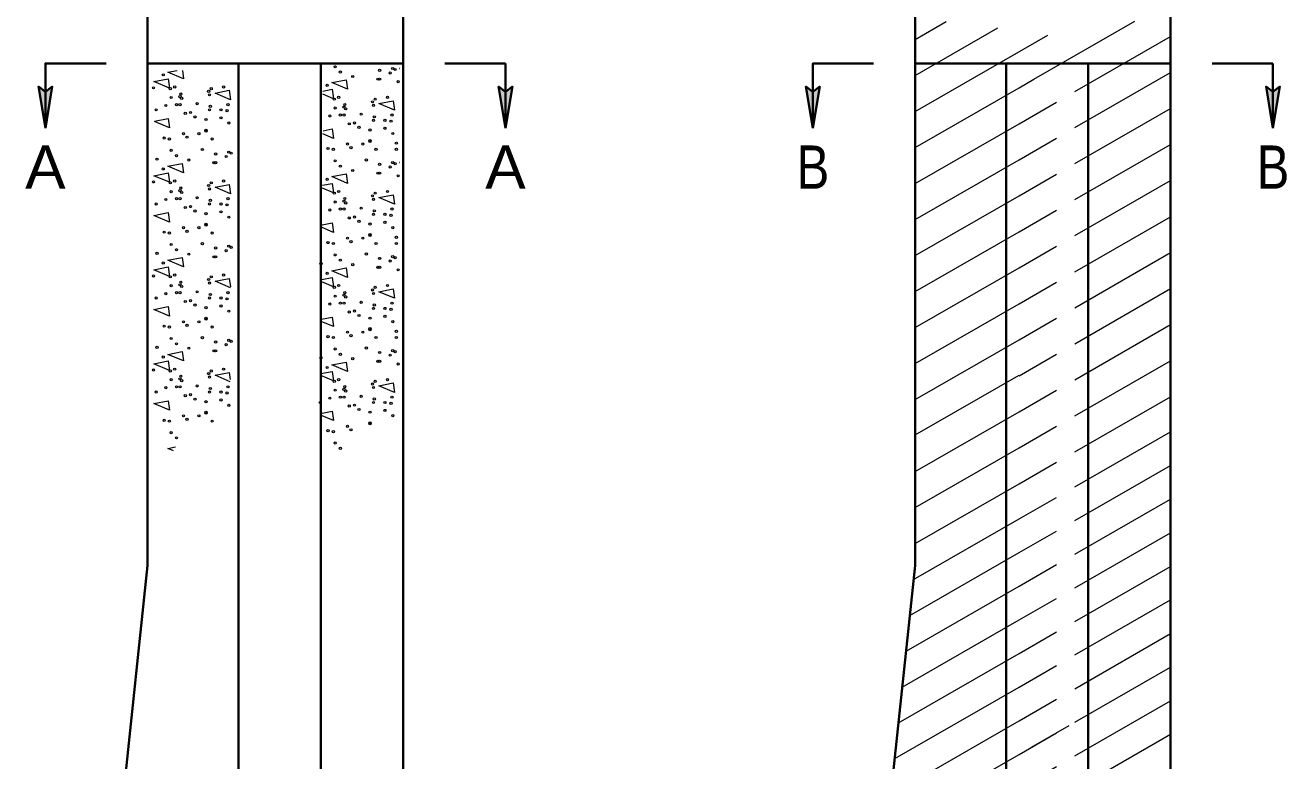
# Model space of a CAD drawing. Extents: x -43.06 to -36.2, y -1.41 to 7.25.
# Drawn here: x -39.109 to -36.195, y 3.886 to 5.585 of the extents above; entities that cross this region are included whole.
import ezdxf
from ezdxf.enums import TextEntityAlignment as Align

# ---------------------------------------------------------------- set-up
doc = ezdxf.new("R2010")
doc.units = 0
doc.header["$LTSCALE"] = 0.024
doc.linetypes.add('SHORT_DASHED', pattern=[2.7, 1.5, -1.2])
for name, color, linetype, lineweight in [('1', 7, 'Continuous', 35), ('10', 7, 'Continuous', 13), ('12', 7, 'Continuous', 53), ('6', 7, 'Continuous', 13)]:
    doc.layers.add(name, color=color, linetype=linetype, lineweight=lineweight)

msp = doc.modelspace()

# ---------------------------------------------------------------- hatches: boundary and pattern name
at = {"layer": '10'}
for points in [[(-39.06275, 5.34733), (-39.04675, 5.4435), (-39.06275, 5.4315), (-39.07875, 5.4435)], [(-37.99992, 5.34733), (-37.98392, 5.4435), (-37.99992, 5.4315), (-38.01592, 5.4435)], [(-37.28975, 5.34733), (-37.27375, 5.4435), (-37.28975, 5.4315), (-37.30575, 5.4435)], [(-36.22692, 5.34733), (-36.21092, 5.4435), (-36.22692, 5.4315), (-36.24292, 5.4435)]]:
    msp.add_hatch(color=256, dxfattribs=at).paths.add_polyline_path(points)

# ---------------------------------------------------------------- linework, layer by layer
at = {"layer": '1'}
for p, q in [((-38.43625, 5.49683), (-38.82642, 5.49683)), ((-38.61625, 5.49683), (-38.61625, 2.96633)), ((-38.43625, 5.49683), (-38.23625, 5.49683)), ((-38.23625, 5.49683), (-38.23625, 4.33667)), ((-36.84342, 5.49683), (-36.84342, 2.96133)), ((-36.65342, 5.49683), (-36.65342, 2.9635)), ((-38.82642, 4.33667), (-38.90542, 3.58917)), ((-38.23625, 4.33667), (-38.23625, 3.32433)), ((-36.46325, 4.33667), (-36.46325, 3.32017))]:
    msp.add_line(p, q, dxfattribs=at)
for points in [[(-38.82642, 7.217), (-38.82642, 5.49683), (-38.82642, 4.33667)], [(-37.05342, 7.217), (-37.05342, 5.49683), (-37.05342, 4.33667), (-37.13258, 3.58917)], [(-38.46175, 6.31517), (-38.23625, 5.97683), (-38.23625, 5.49683)], [(-36.68875, 6.31517), (-36.46325, 5.97683), (-36.46325, 5.49683), (-36.46325, 4.33667)], [(-38.42625, 5.49683), (-38.42625, 2.96633), (-38.71642, 2.96633)], [(-37.05342, 5.49683), (-36.83342, 5.49683), (-36.66342, 5.49683), (-36.46325, 5.49683)]]:
    msp.add_lwpolyline(points, dxfattribs=at)
at = {"layer": '10', "lineweight": 35}
for p, q in [((-37.99992, 5.49683), (-38.14025, 5.49683)), ((-37.99992, 5.49683), (-37.99992, 5.34733)), ((-36.22692, 5.49683), (-36.36725, 5.49683)), ((-36.22692, 5.49683), (-36.22692, 5.34733)), ((-39.07875, 5.4435), (-39.06275, 5.34733)), ((-39.07875, 5.4435), (-39.06275, 5.4315)), ((-39.04675, 5.4435), (-39.06275, 5.34733)), ((-39.04675, 5.4435), (-39.06275, 5.4315)), ((-38.01592, 5.4435), (-37.99992, 5.34733)), ((-38.01592, 5.4435), (-37.99992, 5.4315)), ((-37.98392, 5.4435), (-37.99992, 5.34733)), ((-37.98392, 5.4435), (-37.99992, 5.4315)), ((-37.30575, 5.4435), (-37.28975, 5.34733)), ((-37.30575, 5.4435), (-37.28975, 5.4315)), ((-37.27375, 5.4435), (-37.28975, 5.34733)), ((-37.27375, 5.4435), (-37.28975, 5.4315)), ((-36.24292, 5.4435), (-36.22692, 5.34733)), ((-36.24292, 5.4435), (-36.22692, 5.4315)), ((-36.21092, 5.4435), (-36.22692, 5.34733)), ((-36.21092, 5.4435), (-36.22692, 5.4315))]:
    msp.add_line(p, q, dxfattribs=at)
for points in [[(-38.92242, 5.49683), (-39.06275, 5.49683), (-39.06275, 5.34733)], [(-37.14942, 5.49683), (-37.28975, 5.49683), (-37.28975, 5.39017), (-37.28975, 5.34733)]]:
    msp.add_lwpolyline(points, dxfattribs=at)
for points in [[(-39.06275, 5.34733), (-39.04675, 5.4435), (-39.06275, 5.4315), (-39.07875, 5.4435)], [(-37.99992, 5.34733), (-37.98392, 5.4435), (-37.99992, 5.4315), (-38.01592, 5.4435)], [(-37.28975, 5.34733), (-37.27375, 5.4435), (-37.28975, 5.4315), (-37.30575, 5.4435)], [(-36.22692, 5.34733), (-36.21092, 5.4435), (-36.22692, 5.4315), (-36.24292, 5.4435)]]:
    msp.add_lwpolyline(points, close=True, dxfattribs=at)
at = {"layer": '6'}
for p, q in [((-37.05342, 5.5525), (-36.98208, 5.5935)), ((-37.05342, 5.46933), (-36.86275, 5.579)), ((-36.77958, 5.46033), (-36.54608, 5.59467)), ((-37.05342, 5.386), (-36.74725, 5.56217)), ((-36.68442, 5.43183), (-36.46325, 5.55917)), ((-38.77975, 5.47683), (-38.75842, 5.48083)), ((-38.24525, 5.48517), (-38.24442, 5.48533)), ((-38.24442, 5.48483), (-38.24525, 5.48517)), ((-36.68442, 5.34867), (-36.46325, 5.47583)), ((-37.05342, 5.30283), (-36.81342, 5.44083)), ((-36.68442, 5.26533), (-36.46325, 5.3925)), ((-37.05342, 5.21967), (-36.81342, 5.35767)), ((-36.68442, 5.18217), (-36.46325, 5.30933)), ((-38.24525, 5.26783), (-38.24492, 5.268)), ((-38.24492, 5.26767), (-38.24525, 5.26783)), ((-37.05342, 5.13633), (-36.81342, 5.27433)), ((-36.68442, 5.099), (-36.46325, 5.22617)), ((-37.05342, 5.05317), (-36.81342, 5.19117)), ((-36.68442, 5.01567), (-36.46325, 5.14283)), ((-37.05342, 4.96983), (-36.81342, 5.10783)), ((-36.68442, 4.9325), (-36.46325, 5.05967)), ((-37.05342, 4.88667), (-36.81342, 5.02467)), ((-38.63525, 4.9785), (-38.67075, 4.99367)), ((-36.68442, 4.84933), (-36.46325, 4.9765)), ((-37.05342, 4.8035), (-36.81342, 4.9415)), ((-36.68442, 4.766), (-36.46325, 4.89333)), ((-37.05342, 4.72017), (-36.81342, 4.85817)), ((-36.68442, 4.68283), (-36.46325, 4.81)), ((-38.63558, 4.76133), (-38.67075, 4.77633)), ((-37.05342, 4.63867), (-36.81342, 4.77667)), ((-36.68442, 4.59967), (-36.46325, 4.72683)), ((-37.05342, 4.55383), (-36.81342, 4.69183)), ((-36.68442, 4.5185), (-36.46325, 4.64567)), ((-38.77975, 4.60733), (-38.76208, 4.61083)), ((-38.76692, 4.602), (-38.77975, 4.60733)), ((-37.05342, 4.4705), (-36.81342, 4.6085)), ((-36.68442, 4.44083), (-36.46325, 4.568)), ((-37.05342, 4.38733), (-36.81342, 4.52533)), ((-36.68442, 4.36317), (-36.46325, 4.49033)), ((-37.05692, 4.30433), (-36.81342, 4.44433)), ((-36.68442, 4.28533), (-36.46325, 4.4125)), ((-37.06558, 4.2215), (-36.81342, 4.3665)), ((-36.68442, 4.20767), (-36.46325, 4.33483)), ((-37.07442, 4.13867), (-36.81342, 4.28883)), ((-36.68442, 4.13), (-36.46325, 4.25717)), ((-37.08308, 4.056), (-36.81342, 4.211)), ((-36.68442, 4.05217), (-36.46325, 4.17933)), ((-37.09192, 3.97317), (-36.81342, 4.13333)), ((-36.68442, 3.9745), (-36.46325, 4.10167)), ((-37.10058, 3.8905), (-36.81342, 4.05567)), ((-36.68442, 3.89667), (-36.46325, 4.024)), ((-37.10942, 3.80767), (-36.81342, 3.97783)), ((-36.68442, 3.81983), (-36.46325, 3.947)), ((-37.11825, 3.72483), (-36.81342, 3.90017))]:
    msp.add_line(p, q, dxfattribs=at)
at = {"layer": '6', "linetype": 'SHORT_DASHED'}
for p, q in [((-36.81342, 5.44083), (-36.77958, 5.46033)), ((-36.81342, 5.35767), (-36.68442, 5.43183)), ((-36.81342, 5.27433), (-36.68442, 5.34867)), ((-36.81342, 5.19117), (-36.68442, 5.26533)), ((-36.81342, 5.10783), (-36.68442, 5.18217)), ((-36.81342, 5.02467), (-36.68442, 5.099)), ((-36.81342, 4.9415), (-36.68442, 5.01567)), ((-36.81342, 4.85817), (-36.68442, 4.9325)), ((-36.81342, 4.775), (-36.68442, 4.84933)), ((-36.81342, 4.69183), (-36.68442, 4.766)), ((-36.81342, 4.6085), (-36.68442, 4.68283)), ((-36.81342, 4.52533), (-36.68442, 4.59967)), ((-36.81342, 4.44433), (-36.68442, 4.5185)), ((-36.81342, 4.3665), (-36.68442, 4.44083)), ((-36.81342, 4.28883), (-36.68442, 4.36317)), ((-36.81342, 4.211), (-36.68442, 4.28533)), ((-36.81342, 4.13333), (-36.68442, 4.20767)), ((-36.81342, 4.05567), (-36.68442, 4.13)), ((-36.81342, 3.97783), (-36.68442, 4.05217)), ((-36.81342, 3.90017), (-36.68442, 3.9745)), ((-36.78442, 3.91733), (-36.65525, 3.99167)), ((-36.81342, 3.8225), (-36.68442, 3.89667))]:
    msp.add_line(p, q, dxfattribs=at)
at = {"layer": '6'}
for points in [[(-38.74625, 5.48067), (-38.74375, 5.46133), (-38.77975, 5.47683)], [(-38.42192, 5.433), (-38.40042, 5.43717), (-38.39742, 5.41533), (-38.42192, 5.42583)], [(-38.81092, 5.3635), (-38.77908, 5.36967), (-38.77625, 5.34783), (-38.81092, 5.36267)], [(-38.42125, 5.3415), (-38.40042, 5.34567), (-38.39742, 5.32367), (-38.42142, 5.334)], [(-38.81192, 5.2375), (-38.77908, 5.244), (-38.77625, 5.22217), (-38.81192, 5.23733)], [(-38.42242, 5.2155), (-38.40042, 5.21983), (-38.39742, 5.198), (-38.42242, 5.20867)], [(-38.42325, 5.12383), (-38.40042, 5.12833), (-38.39742, 5.10633), (-38.42325, 5.1175)], [(-38.67075, 4.99367), (-38.63775, 5.00017), (-38.63525, 4.98067)], [(-38.42442, 4.99783), (-38.40042, 5.0025), (-38.39742, 4.98067), (-38.42442, 4.99217)], [(-38.42508, 4.906), (-38.40042, 4.91083), (-38.39742, 4.889), (-38.42525, 4.90083)], [(-38.67075, 4.77633), (-38.63775, 4.78283), (-38.63558, 4.76667)], [(-38.42625, 4.78017), (-38.40042, 4.78517), (-38.39742, 4.76333), (-38.42642, 4.77567)], [(-38.42708, 4.68833), (-38.40042, 4.6935), (-38.39742, 4.67167), (-38.42708, 4.68433)]]:
    msp.add_lwpolyline(points, dxfattribs=at)
for points in [[(-38.81208, 5.45483), (-38.77908, 5.46133), (-38.77625, 5.4395)], [(-38.40092, 5.45267), (-38.36775, 5.45917), (-38.36492, 5.43717)], [(-38.67075, 5.42833), (-38.63775, 5.43483), (-38.63492, 5.413)], [(-38.29208, 5.40433), (-38.25892, 5.41067), (-38.25608, 5.38883)], [(-38.77975, 5.25933), (-38.74658, 5.26583), (-38.74375, 5.244)], [(-38.67075, 5.211), (-38.63775, 5.2175), (-38.63492, 5.19567)], [(-38.40092, 5.23533), (-38.36775, 5.24183), (-38.36492, 5.21983)], [(-38.29208, 5.18683), (-38.25892, 5.19333), (-38.25608, 5.1715)], [(-38.81225, 5.14583), (-38.77908, 5.15233), (-38.77625, 5.1305)], [(-38.77975, 5.042), (-38.74658, 5.0485), (-38.74375, 5.02667)], [(-38.81225, 5.02017), (-38.77908, 5.02667), (-38.77625, 5.00483)], [(-38.40092, 5.018), (-38.36775, 5.02433), (-38.36492, 5.0025)], [(-38.29208, 4.9695), (-38.25892, 4.976), (-38.25608, 4.95417)], [(-38.81225, 4.9285), (-38.77908, 4.935), (-38.77625, 4.91317)], [(-38.81225, 4.80283), (-38.77908, 4.80933), (-38.77625, 4.78733)], [(-38.77975, 4.82467), (-38.74658, 4.83117), (-38.74375, 4.80933)], [(-38.40092, 4.8005), (-38.36775, 4.807), (-38.36492, 4.78517)], [(-38.29208, 4.75217), (-38.25892, 4.75867), (-38.25608, 4.73683)], [(-38.81225, 4.71117), (-38.77908, 4.71767), (-38.77625, 4.69583)]]:
    msp.add_lwpolyline(points, close=True, dxfattribs=at)
for centre in [(-38.39334, 5.4892), (-38.38114, 5.47695), (-38.2906, 5.48104), (-38.26028, 5.4852), (-38.25464, 5.48276), (-38.79044, 5.47055), (-38.35261, 5.46679), (-38.29464, 5.46067), (-38.2906, 5.46067), (-38.26616, 5.47495), (-38.24783, 5.45459), (-38.81284, 5.44051), (-38.77416, 5.43847), (-38.77212, 5.41811), (-38.76396, 5.44255), (-38.75175, 5.42015), (-38.74971, 5.42627), (-38.68566, 5.43235), (-38.68362, 5.42423), (-38.67954, 5.43847), (-38.65106, 5.44255), (-38.41166, 5.44643), (-38.38518, 5.41843), (-38.27228, 5.41843), (-38.80672, 5.38962), (-38.78432, 5.39978), (-38.75992, 5.40182), (-38.75175, 5.40182), (-38.74767, 5.41607), (-38.71211, 5.40386), (-38.68362, 5.38962), (-38.68158, 5.39774), (-38.65714, 5.38962), (-38.64086, 5.40182), (-38.39538, 5.41434), (-38.39334, 5.39398), (-38.37297, 5.39602), (-38.37093, 5.40214), (-38.36889, 5.39194), (-38.30688, 5.40822), (-38.30484, 5.4001), (-38.30076, 5.41434), (-38.73955, 5.38146), (-38.72731, 5.3835), (-38.71715, 5.37334), (-38.69175, 5.36722), (-38.65714, 5.3713), (-38.6429, 5.38758), (-38.40554, 5.37566), (-38.38114, 5.3777), (-38.37297, 5.3777), (-38.33333, 5.37974), (-38.30484, 5.3655), (-38.3028, 5.37362), (-38.27836, 5.3655), (-38.26412, 5.36346), (-38.26208, 5.3777), (-38.74359, 5.33465), (-38.70803, 5.33465), (-38.69175, 5.34277), (-38.69175, 5.34073), (-38.63882, 5.35906), (-38.36077, 5.35734), (-38.34853, 5.35938), (-38.33837, 5.34921), (-38.31296, 5.34309), (-38.27836, 5.34717), (-38.26004, 5.33493), (-38.7884, 5.32445), (-38.7762, 5.32241), (-38.73547, 5.32649), (-38.6775, 5.32241), (-38.36481, 5.31053), (-38.35669, 5.30237), (-38.32925, 5.31053), (-38.31296, 5.31865), (-38.31296, 5.31661), (-38.25191, 5.31257), (-38.80468, 5.2756), (-38.77212, 5.29597), (-38.75992, 5.28372), (-38.73139, 5.27356), (-38.69991, 5.29801), (-38.66938, 5.2878), (-38.64494, 5.28172), (-38.63906, 5.29197), (-38.63342, 5.28952), (-38.40962, 5.30033), (-38.39742, 5.29829), (-38.32113, 5.27388), (-38.29872, 5.29829), (-38.25191, 5.29829), (-38.79044, 5.2532), (-38.67342, 5.26744), (-38.66938, 5.26744), (-38.39334, 5.27184), (-38.38114, 5.2596), (-38.35261, 5.24944), (-38.29464, 5.24332), (-38.2906, 5.26368), (-38.2906, 5.24332), (-38.26616, 5.2576), (-38.26028, 5.26784), (-38.25464, 5.2654), (-38.81284, 5.22315), (-38.77416, 5.22111), (-38.76396, 5.22519), (-38.68566, 5.21499), (-38.67954, 5.22111), (-38.65106, 5.22519), (-38.41166, 5.22908), (-38.24783, 5.23724), (-38.77212, 5.20075), (-38.75175, 5.20279), (-38.74971, 5.20891), (-38.74767, 5.19871), (-38.71211, 5.18651), (-38.68362, 5.20687), (-38.39538, 5.19699), (-38.38518, 5.20107), (-38.37093, 5.18479), (-38.30688, 5.19087), (-38.30076, 5.19699), (-38.27228, 5.20107), (-38.80672, 5.17227), (-38.78432, 5.18243), (-38.75992, 5.18447), (-38.75175, 5.18447), (-38.73955, 5.1641), (-38.72731, 5.16615), (-38.71715, 5.15598), (-38.68362, 5.17227), (-38.68158, 5.18039), (-38.65714, 5.17227), (-38.6429, 5.17023), (-38.64086, 5.18447), (-38.40554, 5.1583), (-38.39334, 5.17663), (-38.38114, 5.16034), (-38.37297, 5.17867), (-38.37297, 5.16034), (-38.36889, 5.17459), (-38.33333, 5.16238), (-38.30484, 5.18275), (-38.3028, 5.15626), (-38.26208, 5.16034), (-38.69175, 5.14986), (-38.65714, 5.15394), (-38.63882, 5.1417), (-38.36077, 5.13998), (-38.34853, 5.14202), (-38.33837, 5.13186), (-38.30484, 5.14814), (-38.27836, 5.14814), (-38.27836, 5.12982), (-38.26412, 5.1461), (-38.7884, 5.1071), (-38.7762, 5.10506), (-38.74359, 5.1173), (-38.73547, 5.10914), (-38.70803, 5.1173), (-38.69175, 5.12542), (-38.69175, 5.12338), (-38.6775, 5.10506), (-38.31296, 5.12574), (-38.31296, 5.10129), (-38.31296, 5.09925), (-38.26004, 5.11758), (-38.77212, 5.07861), (-38.69991, 5.08065), (-38.66938, 5.07045), (-38.63906, 5.07461), (-38.63342, 5.07217), (-38.40962, 5.08297), (-38.39742, 5.08093), (-38.36481, 5.09317), (-38.35669, 5.08501), (-38.32925, 5.09317), (-38.29872, 5.08093), (-38.25191, 5.09521), (-38.25191, 5.08093), (-38.80468, 5.05825), (-38.75992, 5.06637), (-38.73139, 5.05621), (-38.67342, 5.05009), (-38.66938, 5.05009), (-38.64494, 5.06437), (-38.39334, 5.05449), (-38.38114, 5.04225), (-38.32113, 5.05653), (-38.2906, 5.04633), (-38.26616, 5.04025), (-38.26028, 5.05049), (-38.25464, 5.04805), (-38.79044, 5.03584), (-38.4259, 5.03412), (-38.41166, 5.01172), (-38.35261, 5.03208), (-38.29464, 5.02596), (-38.2906, 5.02596), (-38.24783, 5.01988), (-38.81284, 5.0058), (-38.77416, 5.00376), (-38.77212, 4.9834), (-38.76396, 5.00784), (-38.75175, 4.98544), (-38.74971, 4.99156), (-38.74767, 4.98136), (-38.68566, 4.99764), (-38.68362, 4.98952), (-38.67954, 5.00376), (-38.65106, 5.00784), (-38.38518, 4.98372), (-38.27228, 4.98372), (-38.80672, 4.95491), (-38.78432, 4.96507), (-38.75992, 4.96711), (-38.75175, 4.96711), (-38.71211, 4.96915), (-38.68362, 4.95491), (-38.68158, 4.96303), (-38.65714, 4.95491), (-38.6429, 4.95287), (-38.64086, 4.96711), (-38.39538, 4.97964), (-38.39334, 4.95927), (-38.37297, 4.96131), (-38.37093, 4.96743), (-38.36889, 4.95723), (-38.30688, 4.97351), (-38.30484, 4.96539), (-38.30076, 4.97964), (-38.73955, 4.94675), (-38.72731, 4.94879), (-38.71715, 4.93863), (-38.69175, 4.93251), (-38.65714, 4.93659), (-38.63882, 4.92435), (-38.40554, 4.94095), (-38.38114, 4.94299), (-38.37297, 4.94299), (-38.36077, 4.92263), (-38.34853, 4.92467), (-38.33333, 4.94503), (-38.30484, 4.93079), (-38.3028, 4.93891), (-38.27836, 4.93079), (-38.26412, 4.92875), (-38.26208, 4.94299), (-38.74359, 4.89994), (-38.70803, 4.89994), (-38.69175, 4.90806), (-38.69175, 4.90602), (-38.33837, 4.9145), (-38.31296, 4.90838), (-38.27836, 4.91246), (-38.26004, 4.90022), (-38.7884, 4.88974), (-38.7762, 4.8877), (-38.73547, 4.89178), (-38.6775, 4.8877), (-38.40962, 4.86562), (-38.36481, 4.87582), (-38.35669, 4.86766), (-38.32925, 4.87582), (-38.31296, 4.88394), (-38.31296, 4.8819), (-38.25191, 4.87786), (-38.80468, 4.84089), (-38.77212, 4.86126), (-38.75992, 4.84901), (-38.73139, 4.83885), (-38.69991, 4.8633), (-38.66938, 4.8531), (-38.64494, 4.84701), (-38.63906, 4.85726), (-38.63342, 4.85482), (-38.39742, 4.86358), (-38.39334, 4.83713), (-38.32113, 4.83917), (-38.29872, 4.86358), (-38.25191, 4.86358), (-38.79044, 4.81849), (-38.67342, 4.83273), (-38.66938, 4.83273), (-38.4259, 4.81677), (-38.38114, 4.82489), (-38.35261, 4.81473), (-38.29464, 4.80861), (-38.2906, 4.82897), (-38.2906, 4.80861), (-38.26616, 4.82289), (-38.26028, 4.83313), (-38.25464, 4.83069), (-38.81284, 4.78844), (-38.77416, 4.7864), (-38.76396, 4.79049), (-38.68566, 4.78028), (-38.67954, 4.7864), (-38.65106, 4.79049), (-38.41166, 4.79437), (-38.24783, 4.80253), (-38.78432, 4.74772), (-38.77212, 4.76604), (-38.75992, 4.74976), (-38.75175, 4.76808), (-38.75175, 4.74976), (-38.74971, 4.7742), (-38.74767, 4.764), (-38.71211, 4.7518), (-38.68362, 4.77216), (-38.64086, 4.74976), (-38.39538, 4.76228), (-38.38518, 4.76636), (-38.37093, 4.75008), (-38.30688, 4.75616), (-38.30484, 4.74804), (-38.30076, 4.76228), (-38.27228, 4.76636), (-38.80672, 4.73756), (-38.73955, 4.7294), (-38.72731, 4.73144), (-38.71715, 4.72127), (-38.68362, 4.73756), (-38.68158, 4.74568), (-38.65714, 4.73756), (-38.65714, 4.71923), (-38.6429, 4.73552), (-38.40554, 4.72359), (-38.39334, 4.74192), (-38.38114, 4.72563), (-38.37297, 4.74396), (-38.37297, 4.72563), (-38.36889, 4.73988), (-38.33333, 4.72768), (-38.3028, 4.72155), (-38.26208, 4.72563), (-38.69175, 4.71515), (-38.69175, 4.69071), (-38.63882, 4.70699), (-38.42794, 4.71343), (-38.36077, 4.70527), (-38.34853, 4.70731), (-38.33837, 4.69715), (-38.31296, 4.69103), (-38.30484, 4.71343), (-38.27836, 4.71343), (-38.27836, 4.69511), (-38.26412, 4.71139), (-38.7884, 4.67239), (-38.7762, 4.67035), (-38.74359, 4.68259), (-38.73547, 4.67443), (-38.70803, 4.68259), (-38.69175, 4.68867), (-38.6775, 4.67035), (-38.31296, 4.66659), (-38.31296, 4.66454), (-38.26004, 4.68287), (-38.77212, 4.6439), (-38.75992, 4.63166), (-38.40962, 4.64826), (-38.39742, 4.64622), (-38.36481, 4.65846), (-38.35669, 4.6503), (-38.39334, 4.61978), (-38.38114, 4.60754)]:
    msp.add_circle(centre, 0.00252, dxfattribs=at)

# ---------------------------------------------------------------- texts
at = {"layer": '12'}
for s, width, p in [('A', 1.05, (-39.06267, 5.20733)), ('A', 1.05, (-37.99983, 5.20733)), ('B', 0.85, (-37.28967, 5.20733)), ('B', 0.85, (-36.22692, 5.20733))]:
    msp.add_text(s, height=0.1, dxfattribs=dict(at, width=width)).set_placement(p, align=Align.CENTER)

doc.saveas('drawing.dxf')
